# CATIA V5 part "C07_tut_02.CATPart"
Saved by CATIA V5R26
Part number: Part1
Bounding box of the stored display mesh (mm): x 0 to 32, y -32 to 32, z -15 to 36
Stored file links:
  D:\_Deepak\CATIA\CATIA V5 2015 Parts Files\Tutorial Files\Tutorials\c07_catia_v5_6r2015_tut\C07_tut_02.CATPart
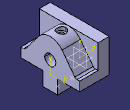
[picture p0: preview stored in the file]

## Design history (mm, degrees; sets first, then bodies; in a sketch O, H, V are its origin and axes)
Body1 (main body)
  Sketch1 on zx-plane, origin (0, 0, 0), H (-1, 0, 0), V (0, 0, 1)
    point P1 (0, 36)
    line L1 (0, 36) -> (0, 0)
    line L2 (0, 0) -> (-32, 0)
    line L3 (0, 36) -> (-12, 36)
    line L4 (-12, 36) -> (-12, 10)
    line L5 (-12, 10) -> (-32, 10)
    line L6 (-32, 10) -> (-32, 0)
    length L2 = 32
    length L3 = 12
    length L6 = 10
    distance L3 L2 = 36
    coincidence: P1 V
    vertical: L1 V, L4 V, L6 V
    horizontal: L2 H, L3 H, L5 H
  Pad1: profile Sketch1, direction (0, 1, 0), length 32, mirrored extent
  Sketch2 on face of Pad1 from Sketch1.L6, origin (32, 0, 0), H (0, 1, 0), V (0, 0, 1)
    arc A1 centre (0, 20) radius 16 from (12.8, 29.6) to (-12.8, 29.6) ccw
    point P1 (0, 20)
    reference projected line E1 (-32, 36) -> (32, 36) from edge [face of Pad1 from Sketch1.L4 | face of Pad1 from Sketch1.L3]
    line L1 (-27.5, 10) -> (27.5, 10)
    point P2 (-27.5, 10)
    point P3 (27.5, 10)
    reference projected line E2 (-32, 10) -> (32, 10) from edge [face of Pad1 from Sketch1.L6 | face of Pad1 from Sketch1.L5]
    line L2 (-27.5, 10) -> (-12.8, 29.6)
    line L3 (27.5, 10) -> (12.8, 29.6)
    radius A1 = 16
    length L1 = 55
    coincidence: P1 V, L1 E2
    tangency: A1 E1, L2 A1, L3 A1
    horizontal: L1 H
    symmetry: P3 P2 V
  Pad2: profile Sketch2, direction (1, 0, 0), up to the existing solid (limit type 2)
  Sketch3 on face of Pad2, origin (32, 0, 0), H (0, 1, 0), V (0, 0, 1)
    line L1 (-8, 0) -> (8, 0)
    line L2 (8, 0) -> (8, -15)
    line L3 (8, -15) -> (-8, -15)
    line L4 (-8, -15) -> (-8, 0)
    reference projected line E1 (-32, 0) -> (32, 0) from edge [face of Pad1 from Sketch1.L2 | face of Pad1 from Sketch1.L6]
    length L2 = 15
    length L3 = 16
    horizontal: L1 H, L3 H
    vertical: L2 V, L4 V
    symmetry: L2 L4 V
    coincidence: L1 E1
  Pad3: profile Sketch3, direction (1, 0, 0), up to face of Pad1 from Sketch1.L1
  Sketch4 on zx-plane, origin (0, 0, 0), H (-1, 0, 0), V (0, 0, 1)
    point P1 (-20, 36)
    reference projected line E1 (0, 36) -> (-12, 36) from edge [face of Pad1 from Sketch1.L3 | end face of Pad1]
    reference projected line E2 (0, 0) -> (0, 36) from edge [face of Pad1 from Sketch1.L1 | end face of Pad1]
    distance P1 E2 = 20
    coincidence: P1 E1
  Sketch5 on {plane type Tangent, Support face of Pad2 from Sketch2.A1, RefPoint Sketch4.P1}, origin (20, 0, 36), H (1, 0, 0), V (0, -1, 0)
    point P1 (0, 0)
    reference projected point E1 (0, 0) from Sketch4.P1
    coincidence: E1 P1
  Hole1: placed by Sketch5, at (20, 0, 36) direction (0, 0, -1), diameter 6, depth 16, V-bottom angle 120, counterbore diameter 10, counterbore depth 4
  Sketch6 on face of Pad2, origin (32, 0, 0), H (0, 1, 0), V (0, 0, 1)
    point P1 (0, 14)
    reference projected line E1 (-8, -15) -> (8, -15) from edge [face of Pad3 from Sketch3.L3 | start face of Pad3]
    distance P1 E1 = 29
    coincidence: P1 V
  Sketch7 on face of Pad2, origin (32, 0, 10), H (0, 1, 0), V (0, 0, 1)
    point P1 (0, 4)
    reference projected point E1 (0, 4) from Sketch6.P1
    coincidence: E1 P1
  Hole2: placed by Sketch7, at (32, 0, 14) direction (-1, 0, 0), diameter 12, depth 24
  Fillet1: radius 3, on edge [face of Pad1 from Sketch1.L5 | face of Pad2 from Sketch2.L3]; edge [face of Pad2 from Sketch2.L2 | face of Pad1 from Sketch1.L5]
  Sketch8 on zx-plane, origin (0, 0, 0), H (-1, 0, 0), V (0, 0, 1)
    point P1 (-24, -15)
    point P2 (-8, -15)
    reference projected line E1 (-32, -15) -> (0, -15) from edge [face of Pad3 from Sketch3.L3 | face of Pad3 from Sketch3.L2]
    reference projected line E2 (-32, -15) -> (0, -15) from edge [face of Pad3 from Sketch3.L3 | face of Pad3 from Sketch3.L2]
    reference projected line E3 (-32, -15) -> (-32, 0) from edge [face of Pad3 from Sketch3.L2 | face of Pad2]
    distance E3 P1 = 8
    distance P2 P1 = 16
    coincidence: P1 E1, P2 E2
  Sketch9 on face of Pad3 from Sketch3.L3, origin (8, 0, -15), H (1, 0, 0), V (0, -1, 0)
    point P1 (0, 0)
    reference projected point E1 (0, 0) from Sketch8.P2
    coincidence: E1 P1
  Hole3: placed by Sketch9, at (8, 0, -15) direction (0, 0, 1), diameter 6, depth 16, V-bottom angle 120
  Sketch10 on face of Pad3 from Sketch3.L3, origin (24, 0, -15), H (1, 0, 0), V (0, -1, 0)
    point P1 (0, 0)
    reference projected point E1 (0, 0) from Sketch8.P1
    coincidence: E1 P1
  Hole4: placed by Sketch10, at (24, 0, -15) direction (0, 0, 1), diameter 6, depth 16, V-bottom angle 120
